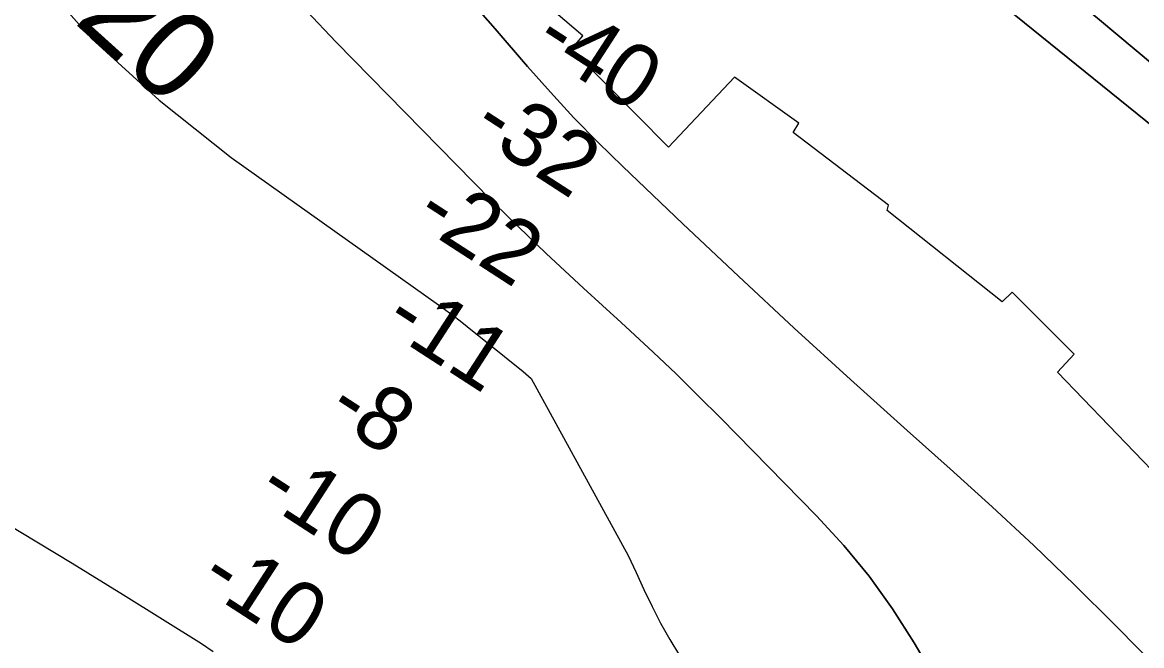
# Model space of a CAD drawing. Extents: x 3245246 to 3283090, y 806824 to 832173.
# Drawn here: x 3267972 to 3269032, y 820682 to 821273 of the extents above; entities that cross this region are included whole.
import ezdxf

# ---------------------------------------------------------------- set-up
doc = ezdxf.new("R2010")
doc.units = 0
for name, color, linetype in [('V-RIVR-RANG', 7, 'Continuous'), ('V-ROAD-CNTR', 7, 'Continuous'), ('V-RRAP-RVMT', 7, 'Continuous'), ('V-RRAP-RVMT-IDEN', 7, 'Continuous'), ('V-TOPO-DPTH', 7, 'Continuous'), ('V-TOPO-MINR', 7, 'Continuous'), ('V-TOPO-MINR-IDEN', 7, 'Continuous')]:
    doc.layers.add(name, color=color, linetype=linetype)

msp = doc.modelspace()

# ---------------------------------------------------------------- linework, layer by layer
at = {"layer": 'V-ROAD-CNTR'}
for points in [[(3268555, 824466.2), (3268928.1, 824288.4), (3269383.1, 824061.9), (3269668.7, 823890.1), (3270076.6, 823640.1), (3270419.3, 823451), (3270842, 823197.9), (3271162.2, 823029.4), (3271548.3, 822792.5), (3271898.4, 822578.4), (3272236.9, 822400.3), (3272509.8, 822239.3), (3272743.9, 822091.3), (3273013.6, 821941.1), (3273341, 821721.2), (3273731.8, 821490.1), (3274189.2, 821175), (3274593.6, 820901.2), (3274916.7, 820684.3), (3275373.2, 820360), (3275676.6, 820161), (3275802.4, 820045.1), (3275896.2, 819928), (3275965.2, 819818.6), (3276015.1, 819699.5), (3276044.4, 819586.7), (3276100.5, 819413), (3276190.9, 819208.3), (3276292.5, 819051.8), (3276415.5, 818926.3), (3276568.2, 818833.9), (3276716.2, 818768.8), (3276924.8, 818729), (3277119.9, 818725), (3277260.8, 818758.2)], [(3265843.1, 823432.9), (3265859, 823417.1), (3265884.4, 823393.5), (3265921.6, 823385.9), (3265988.6, 823351.1), (3266047.2, 823332.3), (3266110.9, 823317.7), (3266174.6, 823302.5), (3266237.9, 823256.1), (3266319, 823213.7), (3266446.2, 823144), (3266598.2, 823070.2), (3266698.3, 823024.2), (3266809.8, 822977.5), (3266902.8, 822954.7), (3266981.5, 822929.4), (3267047, 822922.9), (3267126.7, 822927), (3267196.8, 822934.5), (3267240.8, 822931.2), (3267315.5, 822929), (3267389.5, 822902.9), (3267472.5, 822855.3), (3267548.2, 822799.1), (3267673.2, 822703.2), (3267729.5, 822659.2), (3267800.8, 822580), (3267841.6, 822514.8), (3267890.4, 822443.6), (3267961.5, 822390.3), (3268026.2, 822347.9), (3268097.5, 822313.7), (3268226.8, 822221.5), (3268328.9, 822136.2), (3268438, 822030.2), (3268539.6, 821913.7), (3268611.4, 821855), (3268669.7, 821833), (3268741.6, 821835.2), (3268781, 821862.3), (3268824.2, 821916.6), (3268873.1, 822006.3), (3268932.5, 822098.1), (3268972.1, 822145.5), (3269019.4, 822162), (3269056, 822158.3), (3269086.7, 822138.7), (3269215.7, 821995.6), (3269467.1, 821682.5), (3269665, 821425.3), (3269890.2, 821132.3), (3269935.6, 821060.8), (3269937.8, 820947), (3269911.9, 820878.4), (3269882.4, 820803.4), (3269850.4, 820754.7), (3269820.8, 820702.9), (3269847.5, 820661.4), (3269995.3, 820504.9), (3270135.1, 820342.3), (3270215.8, 820249.2), (3270280.9, 820161.5), (3270409.8, 819983.2), (3270585.2, 819734.7), (3270723.1, 819531.2), (3270847.8, 819342.2), (3270941.2, 819194.9), (3271024.2, 819065), (3271103.7, 818956), (3271217.9, 818809.2), (3271322.1, 818665), (3271450.9, 818481.1), (3271547.8, 818329.9), (3271656.2, 818159), (3271778.9, 817965.4), (3271939, 817707.5), (3272036.6, 817466.5), (3272126.7, 817285.3), (3272211.9, 817051.1), (3272318, 816867.5), (3272429.4, 816683.2), (3272508.6, 816556.2), (3272571.6, 816398.7), (3272670.4, 816197), (3272779.9, 816022.9), (3272872.1, 815803.2), (3272964.7, 815556.6)]]:
    msp.add_spline(points, degree=3, dxfattribs=at)
at = {"layer": 'V-RRAP-RVMT'}
for p, q in [((3268502.9, 821259.9), (3268423.2, 821327.9)), ((3268502.9, 821259.9), (3268423.2, 821327.9)), ((3268492.3, 821247.2), (3268502.9, 821259.9)), ((3268492.3, 821247.2), (3268502.9, 821259.9)), ((3268584.2, 821154.3), (3268492.3, 821247.2)), ((3268584.2, 821154.3), (3268492.3, 821247.2)), ((3268646.5, 821220.7), (3268584.2, 821154.3)), ((3268646.5, 821220.7), (3268584.2, 821154.3)), ((3268707.6, 821177.1), (3268646.5, 821220.7)), ((3268707.6, 821177.1), (3268646.5, 821220.7)), ((3268702.1, 821168.3), (3268707.6, 821177.1)), ((3268702.1, 821168.3), (3268707.6, 821177.1)), ((3268792.6, 821099.5), (3268702.1, 821168.3)), ((3268792.6, 821099.5), (3268702.1, 821168.3)), ((3268791.1, 821094.3), (3268792.6, 821099.5)), ((3268791.1, 821094.3), (3268792.6, 821099.5)), ((3268900.2, 821007.8), (3268791.1, 821094.3)), ((3268900.2, 821007.8), (3268791.1, 821094.3)), ((3268909.5, 821016.9), (3268900.2, 821007.8)), ((3268909.5, 821016.9), (3268900.2, 821007.8)), ((3268968.3, 820958.4), (3268909.5, 821016.9)), ((3268968.3, 820958.4), (3268909.5, 821016.9)), ((3268952.6, 820941.1), (3268968.3, 820958.4)), ((3268952.6, 820941.1), (3268968.3, 820958.4)), ((3269049.8, 820840), (3268952.6, 820941.1)), ((3269049.8, 820840), (3268952.6, 820941.1))]:
    msp.add_line(p, q, dxfattribs=at)
at = {"layer": 'V-TOPO-DPTH'}
for points in [[(3267196.2, 822548.3), (3267930.8, 822068.9), (3267970.5, 822042.8), (3268010.1, 822016.4), (3268049.4, 821989.6), (3268088.6, 821962.7), (3268127.6, 821935.4), (3268166.3, 821907.8), (3268204.8, 821879.8), (3268243, 821851.5), (3268610.9, 821577), (3268659.5, 821540.4), (3268707.9, 821503.5), (3268755.9, 821466.2), (3268803.8, 821428.6), (3268851.3, 821390.6), (3268898.6, 821352.4), (3268945.6, 821313.8), (3268992.4, 821274.9), (3269285.6, 821029.5)], [(3267196.2, 822548.3), (3267930.8, 822068.9), (3267970.5, 822042.8), (3268010.1, 822016.4), (3268049.4, 821989.6), (3268088.6, 821962.7), (3268127.6, 821935.4), (3268166.3, 821907.8), (3268204.8, 821879.8), (3268243, 821851.5), (3268610.9, 821577), (3268659.5, 821540.4), (3268707.9, 821503.5), (3268755.9, 821466.2), (3268803.8, 821428.6), (3268851.3, 821390.6), (3268898.6, 821352.4), (3268945.6, 821313.8), (3268992.4, 821274.9), (3269285.6, 821029.5)], [(3269292.2, 820972.4), (3268855.5, 821325.4), (3268826.8, 821348.5), (3268797.9, 821371.5), (3268768.9, 821394.3), (3268739.8, 821416.9), (3268739, 821417.6), (3268710.1, 821439.7), (3268681.2, 821461.6), (3268652, 821483.4), (3268622.8, 821505), (3268088.4, 821896.4), (3268071.2, 821908.9), (3268054, 821921.3), (3268036.7, 821933.5), (3268019.3, 821945.6), (3268001.7, 821957.6), (3267984.2, 821969.5), (3267966.5, 821981.2), (3267948.7, 821992.8), (3267794.5, 822092.7), (3267699.2, 822153.4)], [(3267699.2, 822153.4), (3267794.5, 822092.7), (3267948.7, 821992.8), (3267966.5, 821981.2), (3267984.2, 821969.5), (3268001.7, 821957.6), (3268019.3, 821945.6), (3268036.7, 821933.5), (3268054, 821921.3), (3268071.2, 821908.9), (3268088.4, 821896.4), (3268622.8, 821505), (3268652, 821483.4), (3268681.2, 821461.6), (3268710.1, 821439.7), (3268739, 821417.6), (3268739.8, 821416.9), (3268768.9, 821394.3), (3268797.9, 821371.5), (3268826.8, 821348.5), (3268855.5, 821325.4), (3269292.2, 820972.4)], [(3267927.3, 821391.6), (3267980.3, 821322.3), (3268037.6, 821257.3), (3268101.5, 821198.8), (3268169.8, 821144.5), (3268366.2, 821005), (3268373.1, 821000), (3268380, 820994.9), (3268386.7, 820989.7), (3268393.4, 820984.5), (3268446.4, 820941.9), (3268453.9, 820935.2), (3268545.8, 820767.5), (3268553.3, 820751.4), (3268560.7, 820735.3), (3268568.5, 820719.3), (3268576.6, 820703.5), (3268585.3, 820688), (3268594.4, 820672.8)], [(3267927.3, 821391.6), (3267980.3, 821322.3), (3268037.6, 821257.3), (3268101.5, 821198.8), (3268169.8, 821144.5), (3268366.2, 821005), (3268373.1, 821000), (3268380, 820994.9), (3268386.7, 820989.7), (3268393.4, 820984.5), (3268446.4, 820941.9), (3268453.9, 820935.2), (3268545.8, 820767.5), (3268553.3, 820751.4), (3268560.7, 820735.3), (3268568.5, 820719.3), (3268576.6, 820703.5), (3268585.3, 820688), (3268594.4, 820672.8)], [(3268387.5, 821303.8), (3268419.9, 821266.6), (3268450.5, 821230.9), (3268472.2, 821206.4), (3268494.4, 821182.3), (3268517.3, 821158.8), (3268540.7, 821135.9), (3268597.7, 821081.6), (3268650.3, 821032.1), (3268703.1, 820982.9), (3268756.4, 820934.3), (3268810.1, 820886), (3268850.9, 820849.6), (3268890.7, 820813.5), (3268930, 820776.9), (3268968.6, 820739.6), (3269006.8, 820701.8), (3269053.4, 820654.8)], [(3269053.4, 820654.8), (3269006.8, 820701.8), (3268968.6, 820739.6), (3268930, 820776.9), (3268890.7, 820813.5), (3268850.9, 820849.6), (3268810.1, 820886), (3268756.4, 820934.3), (3268703.1, 820982.9), (3268650.3, 821032.1), (3268597.7, 821081.6), (3268540.7, 821135.9), (3268517.3, 821158.8), (3268494.4, 821182.3), (3268472.2, 821206.4), (3268450.5, 821230.9), (3268419.9, 821266.6), (3268387.5, 821303.8)], [(3268844.2, 820637.9), (3268816.7, 820684.8), (3268796.2, 820716.9), (3268774.3, 820747.8), (3268750.1, 820777.1), (3268724.4, 820805.2), (3268633.7, 820897.5), (3268612.6, 820918.6), (3268591.3, 820939.5), (3268569.6, 820960.1), (3268547.7, 820980.4), (3268539.3, 820988.1), (3268521.5, 821004.4), (3268503.7, 821020.7), (3268486, 821037.2), (3268468.3, 821053.6), (3268450.8, 821070.2), (3268433.4, 821087), (3268416.3, 821103.9), (3268399.3, 821121.1), (3268269.2, 821253.9), (3268241, 821283.5)], [(3268844.2, 820637.9), (3268816.7, 820684.8), (3268796.2, 820716.9), (3268774.3, 820747.8), (3268750.1, 820777.1), (3268724.4, 820805.2), (3268633.7, 820897.5), (3268612.6, 820918.6), (3268591.3, 820939.5), (3268569.6, 820960.1), (3268547.7, 820980.4), (3268539.3, 820988.1), (3268521.5, 821004.4), (3268503.7, 821020.7), (3268486, 821037.2), (3268468.3, 821053.6), (3268450.8, 821070.2), (3268433.4, 821087), (3268416.3, 821103.9), (3268399.3, 821121.1), (3268269.2, 821253.9), (3268241, 821283.5)]]:
    msp.add_lwpolyline(points, dxfattribs=at)
at = {"layer": 'V-TOPO-MINR'}
for points in [[(3269285.6, 821029.5), (3268992.4, 821274.9), (3268945.6, 821313.8), (3268898.6, 821352.4), (3268851.3, 821390.6), (3268803.8, 821428.6), (3268755.9, 821466.2), (3268707.9, 821503.5), (3268659.5, 821540.4), (3268610.9, 821577), (3268243, 821851.5), (3268204.8, 821879.8), (3268166.3, 821907.8), (3268127.6, 821935.4), (3268088.6, 821962.7), (3268049.4, 821989.6), (3268010.1, 822016.4), (3267970.5, 822042.8), (3267930.8, 822068.9), (3267196.2, 822548.3)], [(3269292.2, 820972.4), (3268855.5, 821325.4), (3268826.8, 821348.5), (3268797.9, 821371.5), (3268768.9, 821394.3), (3268739.8, 821416.9), (3268739, 821417.6), (3268710.1, 821439.7), (3268681.2, 821461.6), (3268652, 821483.4), (3268622.8, 821505), (3268088.4, 821896.4), (3268071.2, 821908.9), (3268054, 821921.3), (3268036.7, 821933.5), (3268019.3, 821945.6), (3268001.7, 821957.6), (3267984.2, 821969.5), (3267966.5, 821981.2), (3267948.7, 821992.8), (3267794.5, 822092.7), (3267699.2, 822153.4)], [(3267927.3, 821391.6), (3267980.3, 821322.3), (3268037.6, 821257.3), (3268101.5, 821198.8), (3268169.8, 821144.5), (3268366.2, 821005), (3268373.1, 821000), (3268380, 820994.9), (3268386.7, 820989.7), (3268393.4, 820984.5), (3268446.4, 820941.9), (3268453.9, 820935.2), (3268545.8, 820767.5), (3268553.3, 820751.4), (3268560.7, 820735.3), (3268568.5, 820719.3), (3268576.6, 820703.5), (3268585.3, 820688), (3268594.4, 820672.8)], [(3268387.5, 821303.8), (3268419.9, 821266.6), (3268450.5, 821230.9), (3268472.2, 821206.4), (3268494.4, 821182.3), (3268517.3, 821158.8), (3268540.7, 821135.9), (3268597.7, 821081.6), (3268650.3, 821032.1), (3268703.1, 820982.9), (3268756.4, 820934.3), (3268810.1, 820886), (3268850.9, 820849.6), (3268890.7, 820813.5), (3268930, 820776.9), (3268968.6, 820739.6), (3269006.8, 820701.8), (3269053.4, 820654.8)], [(3268241, 821283.5), (3268269.2, 821253.9), (3268399.3, 821121.1), (3268416.3, 821103.9), (3268433.4, 821087), (3268450.8, 821070.2), (3268468.3, 821053.6), (3268486, 821037.2), (3268503.7, 821020.7), (3268521.5, 821004.4), (3268539.3, 820988.1), (3268547.7, 820980.4), (3268569.6, 820960.1), (3268591.3, 820939.5), (3268612.6, 820918.6), (3268633.7, 820897.5), (3268724.4, 820805.2), (3268750.1, 820777.1), (3268774.3, 820747.8), (3268796.2, 820716.9), (3268816.7, 820684.8), (3268844.2, 820637.9)], [(3267349.2, 821128.6), (3267470.9, 821076.4), (3267477.4, 821073.5), (3267483.9, 821070.4), (3267490.2, 821067.1), (3267496.5, 821063.6), (3267872.5, 820847.2), (3267921.7, 820818.6), (3267970.6, 820789.6), (3268019.3, 820760.1), (3268067.7, 820730.2), (3268141.6, 820684), (3268152.7, 820676.6)]]:
    msp.add_lwpolyline(points, dxfattribs=at)

# ---------------------------------------------------------------- texts
at = {"layer": 'V-RIVR-RANG'}
for s, p in [('-40', (3268454.1, 821248.6)), ('-32', (3268395.4, 821167.5)), ('-22', (3268341.3, 821083.4)), ('-11', (3268311.9, 820983.3)), ('-8', (3268258, 820899.1)), ('-10', (3268191.7, 820822.9)), ('-10', (3268137.2, 820739))]:
    msp.add_text(s, height=60, rotation=327.0809, dxfattribs=at).set_placement(p)
at = {"layer": 'V-RRAP-RVMT-IDEN'}
msp.add_text('REVET.', height=100, rotation=322.274, dxfattribs=at).set_placement((3268845.8, 821439))
at = {"layer": 'V-TOPO-MINR-IDEN'}
msp.add_text('-20', height=83, rotation=317.9222, dxfattribs=at).set_placement((3267992.3, 821297.8))

doc.saveas('drawing.dxf')
